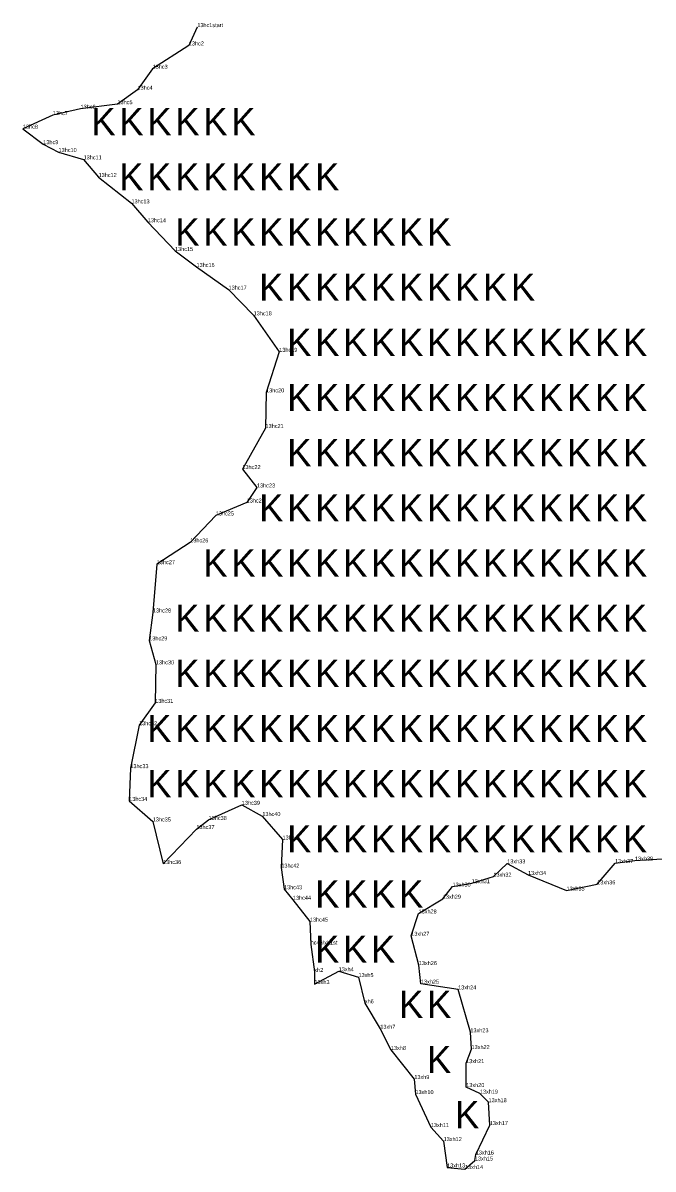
# Model space of a CAD drawing. Extents: x 2072529 to 2268812, y 436423 to 470008.
# Drawn here: x 2247880 to 2248669, y 445976 to 447409 of the extents above; entities that cross this region are included whole.
import ezdxf

# ---------------------------------------------------------------- set-up
doc = ezdxf.new("R2010")
doc.units = 0
for name, color, linetype in [('Old_Level_20', 7, 'Continuous'), ('Old_Level_52', 7, 'Continuous'), ('Old_Level_55', 7, 'Continuous'), ('Old_Level_60', 7, 'Continuous')]:
    doc.layers.add(name, color=color, linetype=linetype)

msp = doc.modelspace()

# ---------------------------------------------------------------- linework, layer by layer
at = {"layer": 'Old_Level_20'}
for p, q in [((2248098.583, 447403.659), (2248098.583, 447403.659)), ((2248088.01, 447380.708), (2248088.01, 447380.708)), ((2248042.716, 447351.65), (2248042.716, 447351.65)), ((2248023.834, 447325.37), (2248023.834, 447325.37)), ((2247998.741, 447307.298), (2247998.741, 447307.298)), ((2247917.848, 447293.632), (2247917.848, 447293.632)), ((2247952.629, 447301.604), (2247952.629, 447301.604)), ((2247880.459, 447276.642), (2247880.459, 447276.642)), ((2247905.916, 447257.292), (2247905.916, 447257.292)), ((2247925.039, 447247.488), (2247925.039, 447247.488)), ((2247956.405, 447238.302), (2247956.405, 447238.302)), ((2247975.159, 447216.209), (2247975.159, 447216.209)), ((2248016.242, 447183.317), (2248016.242, 447183.317)), ((2248036.736, 447159.636), (2248036.736, 447159.636)), ((2248070.729, 447123.692), (2248070.729, 447123.692)), ((2248097.591, 447103.758), (2248097.591, 447103.758)), ((2248137.716, 447075.408), (2248137.716, 447075.408)), ((2248169.062, 447043.295), (2248169.062, 447043.295)), ((2248201.037, 446997.586), (2248201.037, 446997.586)), ((2248184.642, 446946.85), (2248184.642, 446946.85)), ((2248183.951, 446902.316), (2248183.951, 446902.316)), ((2248155.07, 446850.907), (2248155.07, 446850.907)), ((2248173.208, 446827.969), (2248173.208, 446827.969)), ((2248160.359, 446809.129), (2248160.359, 446809.129)), ((2248121.728, 446792.93), (2248121.728, 446792.93)), ((2248089.675, 446759.3), (2248089.675, 446759.3)), ((2248048.002, 446732.033), (2248048.002, 446732.033)), ((2248043.117, 446671.607), (2248043.117, 446671.607)), ((2248038.429, 446636.677), (2248038.429, 446636.677)), ((2248046.884, 446606.721), (2248046.884, 446606.721)), ((2248045.88, 446558.542), (2248045.88, 446558.542)), ((2248025.765, 446530.66), (2248025.765, 446530.66)), ((2248014.837, 446476.931), (2248014.837, 446476.931)), ((2248013.36, 446435.932), (2248013.36, 446435.932)), ((2248154.252, 446431.04), (2248154.252, 446431.04)), ((2248179.904, 446417.071), (2248179.904, 446417.071)), ((2248042.821, 446410.266), (2248042.821, 446410.266)), ((2248112.732, 446412.212), (2248112.732, 446412.212)), ((2248097.439, 446400.705), (2248097.439, 446400.705)), ((2248205.138, 446387.653), (2248205.138, 446387.653)), ((2248646.009, 446361.267), (2248646.009, 446361.267)), ((2248055.831, 446357.068), (2248055.831, 446357.068)), ((2248203.678, 446352.544), (2248203.678, 446352.544)), ((2248486.226, 446357.823), (2248486.226, 446357.823)), ((2248621.086, 446358.196), (2248621.086, 446358.196)), ((2248441.801, 446333.056), (2248441.801, 446333.056)), ((2248468.9, 446341.249), (2248468.9, 446341.249)), ((2248512.299, 446343.409), (2248512.299, 446343.409)), ((2248598.81, 446331.659), (2248598.81, 446331.659)), ((2248207.037, 446325.5), (2248207.037, 446325.5)), ((2248417.851, 446328.814), (2248417.851, 446328.814)), ((2248560.41, 446323.842), (2248560.41, 446323.842)), ((2248218.184, 446312.298), (2248218.184, 446312.298)), ((2248405.626, 446313.703), (2248405.626, 446313.703)), ((2248375.352, 446295.189), (2248375.352, 446295.189)), ((2248239.464, 446285.02), (2248239.464, 446285.02)), ((2248366.159, 446267.282), (2248366.159, 446267.282)), ((2248240.393, 446256.314), (2248240.393, 446256.314)), ((2248375.635, 446230.658), (2248375.635, 446230.658)), ((2248244.989, 446222.091), (2248244.989, 446222.091)), ((2248275.445, 446222.919), (2248275.445, 446222.919)), ((2248300.183, 446215.603), (2248300.183, 446215.603)), ((2248245.126, 446206.867), (2248245.126, 446206.867)), ((2248378.256, 446207.353), (2248378.256, 446207.353)), ((2248424.844, 446200.124), (2248424.844, 446200.124)), ((2248308.153, 446182.826), (2248308.153, 446182.826)), ((2248327.469, 446150.972), (2248327.469, 446150.972)), ((2248440.168, 446146.589), (2248440.168, 446146.589)), ((2248340.718, 446124.549), (2248340.718, 446124.549)), ((2248441.625, 446125.599), (2248441.625, 446125.599)), ((2248434.849, 446107.992), (2248434.849, 446107.992)), ((2248370.027, 446088.17), (2248370.027, 446088.17)), ((2248434.969, 446078.051), (2248434.969, 446078.051)), ((2248371.451, 446069.329), (2248371.451, 446069.329)), ((2248452.023, 446069.903), (2248452.023, 446069.903)), ((2248462.899, 446059.188), (2248462.899, 446059.188)), ((2248464.38, 446030.593), (2248464.38, 446030.593)), ((2248390.666, 446028.091), (2248390.666, 446028.091)), ((2248406.7, 446010.544), (2248406.7, 446010.544)), ((2248445.812, 445986.204), (2248445.812, 445986.204)), ((2248446.85, 445993.678), (2248446.85, 445993.678)), ((2248411.026, 445977.527), (2248411.026, 445977.527)), ((2248433.403, 445975.603), (2248433.403, 445975.603))]:
    msp.add_line(p, q, dxfattribs=at)
at = {"layer": 'Old_Level_52'}
msp.add_lwpolyline([(2248098.583, 447403.659), (2248088.01, 447380.708), (2248042.716, 447351.65), (2248023.834, 447325.37), (2247998.741, 447307.298), (2247952.629, 447301.604), (2247917.848, 447293.632), (2247880.459, 447276.642), (2247905.916, 447257.292), (2247925.039, 447247.488), (2247956.405, 447238.302), (2247975.159, 447216.209), (2248016.242, 447183.317), (2248036.736, 447159.636), (2248070.729, 447123.692), (2248097.591, 447103.758), (2248137.716, 447075.408), (2248169.062, 447043.295), (2248201.037, 446997.586), (2248184.642, 446946.85), (2248183.951, 446902.316), (2248155.07, 446850.907), (2248173.208, 446827.969), (2248160.359, 446809.129), (2248121.728, 446792.93), (2248089.675, 446759.3), (2248048.002, 446732.033), (2248043.117, 446671.607), (2248038.429, 446636.677), (2248046.884, 446606.721), (2248045.88, 446558.542), (2248025.765, 446530.66), (2248014.837, 446476.931), (2248013.36, 446435.932), (2248042.821, 446410.266), (2248055.831, 446357.068), (2248097.439, 446400.705), (2248112.732, 446412.212), (2248154.252, 446431.04), (2248179.904, 446417.071), (2248205.138, 446387.653), (2248203.678, 446352.544), (2248207.037, 446325.5), (2248218.184, 446312.298), (2248239.464, 446285.02), (2248240.393, 446256.314), (2248244.989, 446222.091), (2248245.126, 446206.867), (2248275.445, 446222.919), (2248300.183, 446215.603), (2248308.153, 446182.826), (2248327.469, 446150.972), (2248340.718, 446124.549), (2248370.027, 446088.17), (2248371.451, 446069.329), (2248390.666, 446028.091), (2248406.7, 446010.544), (2248411.026, 445977.527), (2248433.403, 445975.603), (2248445.812, 445986.204), (2248446.85, 445993.678), (2248464.38, 446030.593), (2248462.899, 446059.188), (2248452.023, 446069.903), (2248434.969, 446078.051), (2248434.849, 446107.992), (2248441.625, 446125.599), (2248440.168, 446146.589), (2248424.844, 446200.124), (2248378.256, 446207.353), (2248375.635, 446230.658), (2248366.159, 446267.282), (2248375.352, 446295.189), (2248405.626, 446313.703), (2248417.851, 446328.814), (2248441.801, 446333.056), (2248468.9, 446341.249), (2248486.226, 446357.823), (2248512.299, 446343.409), (2248560.41, 446323.842), (2248598.81, 446331.659), (2248621.086, 446358.196), (2248646.009, 446361.267), (2248679.966, 446363.608)], dxfattribs=at)

# ---------------------------------------------------------------- texts
at = {"layer": 'Old_Level_55'}
for p in [(2247965.96, 447268.486), (2248000.96, 447268.486), (2248035.96, 447268.486), (2248070.96, 447268.486), (2248105.96, 447268.486), (2248140.96, 447268.486), (2248000.96, 447199.486), (2248035.96, 447199.486), (2248070.96, 447199.486), (2248105.96, 447199.486), (2248140.96, 447199.486), (2248175.96, 447199.486), (2248210.96, 447199.486), (2248245.96, 447199.486), (2248070.96, 447130.486), (2248105.96, 447130.486), (2248140.96, 447130.486), (2248175.96, 447130.486), (2248210.96, 447130.486), (2248245.96, 447130.486), (2248280.96, 447130.486), (2248315.96, 447130.486), (2248350.96, 447130.486), (2248385.96, 447130.486), (2248175.96, 447061.486), (2248210.96, 447061.486), (2248245.96, 447061.486), (2248280.96, 447061.486), (2248315.96, 447061.486), (2248350.96, 447061.486), (2248385.96, 447061.486), (2248420.96, 447061.486), (2248455.96, 447061.486), (2248490.96, 447061.486), (2248210.96, 446992.486), (2248245.96, 446992.486), (2248280.96, 446992.486), (2248315.96, 446992.486), (2248350.96, 446992.486), (2248385.96, 446992.486), (2248420.96, 446992.486), (2248455.96, 446992.486), (2248490.96, 446992.486), (2248525.96, 446992.486), (2248560.96, 446992.486), (2248595.96, 446992.486), (2248630.96, 446992.486), (2248210.96, 446923.486), (2248245.96, 446923.486), (2248280.96, 446923.486), (2248315.96, 446923.486), (2248350.96, 446923.486), (2248385.96, 446923.486), (2248420.96, 446923.486), (2248455.96, 446923.486), (2248490.96, 446923.486), (2248525.96, 446923.486), (2248560.96, 446923.486), (2248595.96, 446923.486), (2248630.96, 446923.486), (2248210.96, 446854.486), (2248245.96, 446854.486), (2248280.96, 446854.486), (2248315.96, 446854.486), (2248350.96, 446854.486), (2248385.96, 446854.486), (2248420.96, 446854.486), (2248455.96, 446854.486), (2248490.96, 446854.486), (2248525.96, 446854.486), (2248560.96, 446854.486), (2248595.96, 446854.486), (2248630.96, 446854.486), (2248175.96, 446785.486), (2248210.96, 446785.486), (2248245.96, 446785.486), (2248280.96, 446785.486), (2248315.96, 446785.486), (2248350.96, 446785.486), (2248385.96, 446785.486), (2248420.96, 446785.486), (2248455.96, 446785.486), (2248490.96, 446785.486), (2248525.96, 446785.486), (2248560.96, 446785.486), (2248595.96, 446785.486), (2248630.96, 446785.486), (2248105.96, 446716.486), (2248140.96, 446716.486), (2248175.96, 446716.486), (2248210.96, 446716.486), (2248245.96, 446716.486), (2248280.96, 446716.486), (2248315.96, 446716.486), (2248350.96, 446716.486), (2248385.96, 446716.486), (2248420.96, 446716.486), (2248455.96, 446716.486), (2248490.96, 446716.486), (2248525.96, 446716.486), (2248560.96, 446716.486), (2248595.96, 446716.486), (2248630.96, 446716.486), (2248070.96, 446647.486), (2248105.96, 446647.486), (2248140.96, 446647.486), (2248175.96, 446647.486), (2248210.96, 446647.486), (2248245.96, 446647.486), (2248280.96, 446647.486), (2248315.96, 446647.486), (2248350.96, 446647.486), (2248385.96, 446647.486), (2248420.96, 446647.486), (2248455.96, 446647.486), (2248490.96, 446647.486), (2248525.96, 446647.486), (2248560.96, 446647.486), (2248595.96, 446647.486), (2248630.96, 446647.486), (2248070.96, 446578.486), (2248105.96, 446578.486), (2248140.96, 446578.486), (2248175.96, 446578.486), (2248210.96, 446578.486), (2248245.96, 446578.486), (2248280.96, 446578.486), (2248315.96, 446578.486), (2248350.96, 446578.486), (2248385.96, 446578.486), (2248420.96, 446578.486), (2248455.96, 446578.486), (2248490.96, 446578.486), (2248525.96, 446578.486), (2248560.96, 446578.486), (2248595.96, 446578.486), (2248630.96, 446578.486), (2248035.96, 446509.486), (2248070.96, 446509.486), (2248105.96, 446509.486), (2248140.96, 446509.486), (2248175.96, 446509.486), (2248210.96, 446509.486), (2248245.96, 446509.486), (2248280.96, 446509.486), (2248315.96, 446509.486), (2248350.96, 446509.486), (2248385.96, 446509.486), (2248420.96, 446509.486), (2248455.96, 446509.486), (2248490.96, 446509.486), (2248525.96, 446509.486), (2248560.96, 446509.486), (2248595.96, 446509.486), (2248630.96, 446509.486), (2248035.96, 446440.486), (2248070.96, 446440.486), (2248105.96, 446440.486), (2248140.96, 446440.486), (2248175.96, 446440.486), (2248210.96, 446440.486), (2248245.96, 446440.486), (2248280.96, 446440.486), (2248315.96, 446440.486), (2248350.96, 446440.486), (2248385.96, 446440.486), (2248420.96, 446440.486), (2248455.96, 446440.486), (2248490.96, 446440.486), (2248525.96, 446440.486), (2248560.96, 446440.486), (2248595.96, 446440.486), (2248630.96, 446440.486), (2248210.96, 446371.486), (2248245.96, 446371.486), (2248280.96, 446371.486), (2248315.96, 446371.486), (2248350.96, 446371.486), (2248385.96, 446371.486), (2248420.96, 446371.486), (2248455.96, 446371.486), (2248490.96, 446371.486), (2248525.96, 446371.486), (2248560.96, 446371.486), (2248595.96, 446371.486), (2248630.96, 446371.486), (2248245.96, 446302.486), (2248280.96, 446302.486), (2248315.96, 446302.486), (2248350.96, 446302.486), (2248245.96, 446233.486), (2248280.96, 446233.486), (2248315.96, 446233.486), (2248350.96, 446164.486), (2248385.96, 446164.486), (2248385.96, 446095.486), (2248420.96, 446026.486)]:
    msp.add_text('K', height=34, dxfattribs=at).set_placement(p)
at = {"layer": 'Old_Level_60'}
for s, p in [('13hc1start', (2248098.583, 447403.659)), ('13hc2', (2248088.01, 447380.708)), ('13hc3', (2248042.716, 447351.65)), ('13hc4', (2248023.834, 447325.37)), ('13hc6', (2247952.629, 447301.604)), ('13hc5', (2247998.741, 447307.298)), ('13hc7', (2247917.848, 447293.632)), ('13hc8', (2247880.459, 447276.642)), ('13hc9', (2247905.916, 447257.292)), ('13hc10', (2247925.039, 447247.488)), ('13hc11', (2247956.405, 447238.302)), ('13hc12', (2247975.159, 447216.209)), ('13hc13', (2248016.242, 447183.317)), ('13hc14', (2248036.736, 447159.636)), ('13hc15', (2248070.729, 447123.692)), ('13hc16', (2248097.591, 447103.758)), ('13hc17', (2248137.716, 447075.408)), ('13hc18', (2248169.062, 447043.295)), ('13hc19', (2248201.037, 446997.586)), ('13hc20', (2248184.642, 446946.85)), ('13hc21', (2248183.951, 446902.316)), ('13hc22', (2248155.07, 446850.907)), ('13hc23', (2248173.208, 446827.969)), ('13hc24', (2248160.359, 446809.129)), ('13hc25', (2248121.728, 446792.93)), ('13hc26', (2248089.675, 446759.3)), ('13hc27', (2248048.002, 446732.033)), ('13hc28', (2248043.117, 446671.607)), ('13hc29', (2248038.429, 446636.677)), ('13hc30', (2248046.884, 446606.721)), ('13hc31', (2248045.88, 446558.542)), ('13hc32', (2248025.765, 446530.66)), ('13hc33', (2248014.837, 446476.931)), ('13hc34', (2248013.36, 446435.932)), ('13hc39', (2248154.252, 446431.04)), ('13hc38', (2248112.732, 446412.212)), ('13hc40', (2248179.904, 446417.071)), ('13hc35', (2248042.821, 446410.266)), ('13hc37', (2248097.439, 446400.705)), ('13hc41', (2248205.138, 446387.653)), ('13hc36', (2248055.831, 446357.068)), ('13xh33', (2248486.226, 446357.823)), ('13xh37', (2248621.086, 446358.196)), ('13xh38', (2248646.009, 446361.267)), ('13hc42', (2248203.678, 446352.544)), ('13xh32', (2248468.9, 446341.249)), ('13xh34', (2248512.299, 446343.409)), ('13hc43', (2248207.037, 446325.5)), ('13xh30', (2248417.851, 446328.814)), ('13xh31', (2248441.801, 446333.056)), ('13xh36', (2248598.81, 446331.659)), ('13hc44', (2248218.184, 446312.298)), ('13xh29', (2248405.626, 446313.703)), ('13xh35', (2248560.41, 446323.842)), ('13hc45', (2248239.464, 446285.02)), ('13xh28', (2248375.352, 446295.189)), ('hc46/xh1st', (2248240.393, 446256.314)), ('13xh27', (2248366.159, 446267.282)), ('13xh26', (2248375.635, 446230.658)), ('xh2', (2248244.989, 446222.091)), ('13xh4', (2248275.445, 446222.919)), ('13xh5', (2248300.183, 446215.603)), ('13xh3', (2248245.126, 446206.867)), ('13xh25', (2248378.256, 446207.353)), ('13xh24', (2248424.844, 446200.124)), ('xh6', (2248308.153, 446182.826)), ('13xh7', (2248327.469, 446150.972)), ('13xh23', (2248440.168, 446146.589)), ('13xh8', (2248340.718, 446124.549)), ('13xh22', (2248441.625, 446125.599)), ('13xh21', (2248434.849, 446107.992)), ('13xh9', (2248370.027, 446088.17)), ('13xh10', (2248371.451, 446069.329)), ('13xh20', (2248434.969, 446078.051)), ('13xh19', (2248452.023, 446069.903)), ('13xh18', (2248462.899, 446059.188)), ('13xh11', (2248390.666, 446028.091)), ('13xh17', (2248464.38, 446030.593)), ('13xh12', (2248406.7, 446010.544)), ('13xh15', (2248445.812, 445986.204)), ('13xh16', (2248446.85, 445993.678)), ('13xh13', (2248411.026, 445977.527)), ('13xh14', (2248433.403, 445975.603))]:
    msp.add_text(s, height=5, dxfattribs=at).set_placement(p)

doc.saveas('drawing.dxf')
